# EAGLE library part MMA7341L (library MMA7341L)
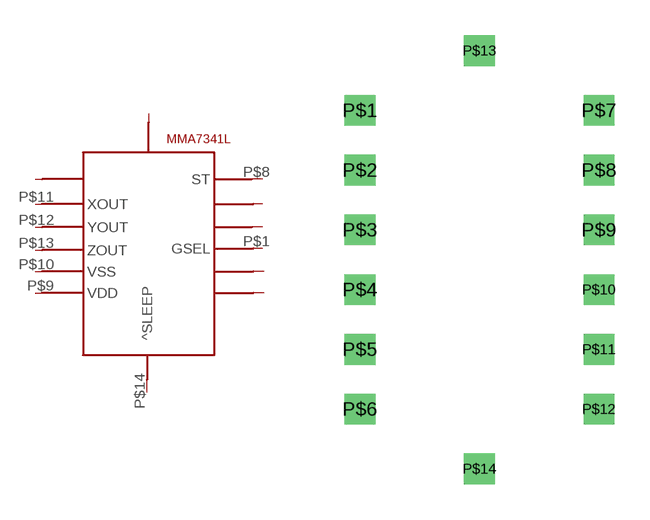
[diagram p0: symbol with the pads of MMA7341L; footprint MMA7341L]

Designator prefix -

## MMA7341L  [MMA7341L]
P$1  GSEL
P$2  N/C
P$3  P$8
P$4  P$9
P$5  P$11
P$6  P$12
P$7  P$13
P$8  ST
P$9  VDD
P$10  VSS
P$11  XOUT
P$12  YOUT
P$13  ZOUT
P$14  ^SLEEP

## Footprint MMA7341L (pad centres in mm)
Accelerometru
drill 0.8 square: P$1 -10.16,7.62; P$2 -10.16,5.08; P$3 -10.16,2.54; P$4 -10.16,0; P$5 -10.16,-2.54; P$6 -10.16,-5.08; P$7 0,7.62; P$8 0,5.08; P$9 0,2.54; P$10 0,0; P$11 0,-2.54; P$12 0,-5.08; P$13 -5.08,10.16; P$14 -5.08,-7.62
